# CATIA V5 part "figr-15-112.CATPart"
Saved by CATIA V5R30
Part number: Part1
Bounding box of the stored display mesh (mm): x -55.37 to 68.649, y -21.457 to 35.984, z 0 to 57.441
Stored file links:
  D:\PROJECTS\CATIA V56R 2020\Resources\Parts File\c15_catia_v5_6r2020_prt\figr-15-112.CATPart
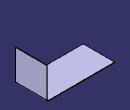
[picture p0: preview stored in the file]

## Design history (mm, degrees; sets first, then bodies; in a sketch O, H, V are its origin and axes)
SheetMetalParameters1: Thickness 1, BendRadius 2, KFactor 0.400515 {= log(min(100,max(20*SheetMetalParameters1.BendRadius,SheetMetalParameters1.Thickness)/SheetMetalParameters1.Thickness))/log(100)/2}, ReliefRadialLength 1, ReliefAxialLength 2, MinimumBendRadius 0
Body1 (main body)
  Sketch1 on xy-plane, origin (0, 0, 0), H (1, 0, 0), V (0, 1, 0)
    line L1 (-55.3695, 35.9836) -> (67.649, 35.9836)
    line L2 (67.649, 35.9836) -> (67.649, -21.4575)
    line L3 (67.649, -21.4575) -> (-55.3695, -21.4575)
    line L4 (-55.3695, -21.4575) -> (-55.3695, 35.9836)
    horizontal: L1 H, L3 H
    vertical: L2 V, L4 V
  Wall1: Thickness 1, Profile Sketch1
  d_NewWallOnEdge1: NewWallOnEdge_Edge edge [face of Wall1 | face of Wall1], NewWallOnEdge_Length 57.4411, NewWallOnEdge_HeightLimitOffset 0, NewWallOnEdge_WidthOffset1 0, NewWallOnEdge_WidthOffset2 0, NewWallOnEdge_Angle 90, NewWallOnEdge_BendRadiusValue 2 {= SheetMetalParameters1.BendRadius}, NewWallOnEdge_BendTable SheetMetalParameters1, KFacteur 0.400515 {= log(min(100,max(20*d_NewWallOnEdge1.Radius,SheetMetalParameters1.Thickness)/SheetMetalParameters1.Thickness))/log(100)/2}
